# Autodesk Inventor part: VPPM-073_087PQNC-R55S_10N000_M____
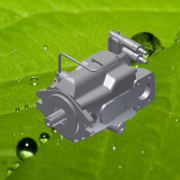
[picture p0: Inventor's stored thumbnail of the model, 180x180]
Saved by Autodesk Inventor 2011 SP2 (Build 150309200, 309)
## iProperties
Created: 2013-08
Part Number: VPPM-073_087PQNC-R55S_10N000_M____
Document SubType Name: Modeling
Designer: dorohin
Density: 1 g/cm^3
Author: dorohin
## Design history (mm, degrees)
derived "VPPM-073PQNC-R55S_10N000_M060_front.iam"
node "Твердое тело1"
node "48416111-R.ipt:1"
node "23390030.ipt:1"
sketch "36190010.ipt:1"
sketch "36190010.ipt:2"
sketch "36190010.ipt:3"
sketch "36190010.ipt:4"
sketch "42136810.ipt:1"
sketch "42136760.ipt:1"
sketch "42136810.ipt:2"
sketch "42136760.ipt:2"
sketch "06870010.ipt:1"
sketch "06870000.ipt:1"
sketch "0530055.ipt:1"
sketch "0530055.ipt:2"
sketch "0530055.ipt:3"
sketch "0530055.ipt:4"
sketch "0551527.ipt:1"
sketch "0570181.ipt:1"
sketch "0770325.ipt:1"
sketch "0530528_.ipt:1"
sketch "0770325.ipt:2"
sketch "36740210.ipt:1"
sketch "0551527.ipt:2"
sketch "0570181.ipt:2"
sketch "0770325.ipt:3"
sketch "0530528_.ipt:2"
sketch "0770325.ipt:4"
sketch "36740210.ipt:2"
sketch "45381506.ipt:2"
sketch "50382620.ipt:1"
sketch "45381536.ipt:1"
node "47555520.ipt:1"
sketch "42799950.ipt:1"
node "39790100.ipt:1"
node "40880500.ipt:1"
sketch "0771483_.ipt:1"
sketch "3001200200-00.ipt:1"
sketch "06870020.ipt:1"
sketch "0530048.ipt:1"
sketch "0530048.ipt:2"
sketch "0570180_.ipt:1"
sketch "45381506.ipt:3"
